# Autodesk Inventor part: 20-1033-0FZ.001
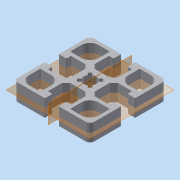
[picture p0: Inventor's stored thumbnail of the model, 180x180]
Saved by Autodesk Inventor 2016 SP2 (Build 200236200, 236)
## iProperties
Created: 2007-12
Document SubType Name: Modeling
Designer: Administrator
Density: 2.75 g/cm^3
Material: EN AW-6063 T66
Description: Profil 45x45 F
Mass: 20.4209 g
Surface Area: 68.0612 cm^2
Volume: 7.4258 cm^3
Part Number: 20-1033-0FZ.001
Vendor: MiniTec
Appearance: Aluminium - flach - Version 1.1
M8x20_Stck: 0
PV_Stck: 0
Länge: 10.0 mm
Lieferantennr: 72401
Zeichnungsnr: 20-1033-0FZ.001
MiniTec_ID: 201033/0
Teileart: ART
Lieferant: MiniTec™
Bezeichnung: Profil 45x45 F
Artikelnr: 201033/0
Bemerkung: eloxiert E6/EV1
M10x25_Stck: 0
M12_Stck: 0
BfGv_Stck: 0
Title: Profil 45x45 F
Author: Administrator
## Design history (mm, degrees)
sketch "Skizze1"
  geometry: L1 (-22.2, 4.1)-(-18.5, 4.1); L2 (-18, 4.6)-(-18, 6.5); L3 (-17.7, 6.8)-(-9.5, 6.8); L4 (-9.5, 6.8)-(-7.2, 4.5); L5 (-7.2, 4.5)-(-7.2, -4.5); L6 (-7.2, -4.5)-(-9.5, -6.8); L7 (-9.5, -6.8)-(-17.7, -6.8); L8 (-18, -6.5)-(-18, -4.6); L9 (-18.5, -4.1)-(-22.2, -4.1); L10 (-22.5, 4.4)-(-22.5, 20); L11 (-22.5, -20)-(-22.5, -4.4); L12 (-4.4, -22.5)-(-20, -22.5); L13 (-4.1, -22.2)-(-4.1, -18.5); L14 (-4.6, -18)-(-6.5, -18); L15 (-6.8, -17.7)-(-6.8, -9.5); L16 (-6.8, -9.5)-(-4.5, -7.2); L17 (-4.5, -7.2)-(4.5, -7.2); L18 (4.5, -7.2)-(6.8, -9.5); L19 (6.8, -9.5)-(6.8, -17.7); L20 (6.5, -18)-(4.6, -18); L21 (4.1, -18.5)-(4.1, -22.2); L22 (20, -22.5)-(4.4, -22.5); L23 (22.5, -4.4)-(22.5, -20); L24 (22.2, -4.1)-(18.5, -4.1); L25 (18, -4.6)-(18, -6.5); L26 (17.7, -6.8)-(9.5, -6.8); L27 (9.5, -6.8)-(7.2, -4.5); L28 (7.2, -4.5)-(7.2, 4.5); L29 (7.2, 4.5)-(9.5, 6.8); L30 (9.5, 6.8)-(17.7, 6.8); L31 (18, 6.5)-(18, 4.6); L32 (18.5, 4.1)-(22.2, 4.1); L33 (22.5, 20)-(22.5, 4.4); L34 (4.4, 22.5)-(20, 22.5); L35 (4.1, 22.2)-(4.1, 18.5); L36 (4.6, 18)-(6.5, 18); L37 (6.8, 17.7)-(6.8, 9.5); L38 (6.8, 9.5)-(4.5, 7.2); L39 (4.5, 7.2)-(-4.5, 7.2); L40 (-4.5, 7.2)-(-6.8, 9.5); L41 (-6.8, 9.5)-(-6.8, 17.7); L42 (-6.5, 18)-(-4.6, 18); L43 (-4.1, 18.5)-(-4.1, 22.2); L44 (-20, 22.5)-(-4.4, 22.5); L45 (-2.97, 4.384)-(-2.005, 3.419); L46 (2.005, 3.419)-(2.97, 4.384); L47 (3.394, 4.384)-(4.384, 3.394); L48 (4.384, 2.97)-(3.419, 2.005); L49 (3.419, -2.005)-(4.384, -2.97); L50 (4.384, -3.394)-(3.394, -4.384); L51 (2.97, -4.384)-(2.005, -3.419); L52 (-2.005, -3.419)-(-2.97, -4.384); L53 (-3.394, -4.384)-(-4.384, -3.394); L54 (-4.384, -2.97)-(-3.419, -2.005); L55 (-3.419, 2.005)-(-4.384, 2.97); L56 (-4.384, 3.394)-(-3.394, 4.384); L57 (-8.8, -13.8)-(-8.8, -20); L58 (-9.3, -20.5)-(-15.5, -20.5); L59 (-20.5, -15.5)-(-20.5, -9.3); L60 (-20, -8.8)-(-13.8, -8.8); L61 (13.8, -8.8)-(20, -8.8); L62 (20.5, -9.3)-(20.5, -15.5); L63 (15.5, -20.5)-(9.3, -20.5); L64 (8.8, -20)-(8.8, -13.8)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; A1 r 0.3 centre (-22.2, 4.4) between (-22.5, 4.4) and (-22.2, 4.1); A2 r 0.5 centre (-18.5, 4.6) between (-18.5, 4.1) and (-18, 4.6); A3 r 0.3 centre (-17.7, 6.5) between (-17.7, 6.8) and (-18, 6.5); A4 r 0.3 centre (-17.7, -6.5) between (-18, -6.5) and (-17.7, -6.8); A5 r 0.5 centre (-18.5, -4.6) between (-18, -4.6) and (-18.5, -4.1); A6 r 0.3 centre (-22.2, -4.4) between (-22.2, -4.1) and (-22.5, -4.4); A7 r 2.5 centre (-20, -20) between (-22.5, -20) and (-20, -22.5); A8 r 0.3 centre (-4.4, -22.2) between (-4.4, -22.5) and (-4.1, -22.2); A9 r 0.5 centre (-4.6, -18.5) between (-4.1, -18.5) and (-4.6, -18); A10 r 0.3 centre (-6.5, -17.7) between (-6.8, -17.7) and (-6.5, -18); A11 r 0.3 centre (6.5, -17.7) between (6.5, -18) and (6.8, -17.7); A12 r 0.5 centre (4.6, -18.5) between (4.6, -18) and (4.1, -18.5); A13 r 0.3 centre (4.4, -22.2) between (4.1, -22.2) and (4.4, -22.5); A14 r 2.5 centre (20, -20) between (20, -22.5) and (22.5, -20); A15 r 0.3 centre (22.2, -4.4) between (22.5, -4.4) and (22.2, -4.1); A16 r 0.5 centre (18.5, -4.6) between (18.5, -4.1) and (18, -4.6); A17 r 0.3 centre (17.7, -6.5) between (17.7, -6.8) and (18, -6.5); A18 r 0.3 centre (17.7, 6.5) between (18, 6.5) and (17.7, 6.8); A19 r 0.5 centre (18.5, 4.6) between (18, 4.6) and (18.5, 4.1); A20 r 0.3 centre (22.2, 4.4) between (22.2, 4.1) and (22.5, 4.4); A21 r 2.5 centre (20, 20) between (22.5, 20) and (20, 22.5); A22 r 0.3 centre (4.4, 22.2) between (4.4, 22.5) and (4.1, 22.2); A23 r 0.5 centre (4.6, 18.5) between (4.1, 18.5) and (4.6, 18); A24 r 0.3 centre (6.5, 17.7) between (6.8, 17.7) and (6.5, 18); A25 r 0.3 centre (-6.5, 17.7) between (-6.5, 18) and (-6.8, 17.7); A26 r 0.5 centre (-4.6, 18.5) between (-4.6, 18) and (-4.1, 18.5); A27 r 0.3 centre (-4.4, 22.2) between (-4.1, 22.2) and (-4.4, 22.5); A28 r 2.5 centre (-20, 20) between (-20, 22.5) and (-22.5, 20); A29 r 0.3 centre (-1.793, 3.631) between (-2.005, 3.419) and (-1.66, 3.362); A30 r 3.75 centre (0, 0) between (1.66, 3.362) and (-1.66, 3.362); A31 r 0.3 centre (1.793, 3.631) between (1.66, 3.362) and (2.005, 3.419); A32 r 0.3 centre (3.182, 4.172) between (3.394, 4.384) and (2.97, 4.384); A33 r 0.3 centre (4.172, 3.182) between (4.384, 2.97) and (4.384, 3.394); A34 r 0.3 centre (3.631, 1.793) between (3.419, 2.005) and (3.362, 1.66); A35 r 3.75 centre (0, 0) between (3.362, -1.66) and (3.362, 1.66); A36 r 0.3 centre (3.631, -1.793) between (3.362, -1.66) and (3.419, -2.005); A37 r 0.3 centre (4.172, -3.182) between (4.384, -3.394) and (4.384, -2.97); A38 r 0.3 centre (3.182, -4.172) between (2.97, -4.384) and (3.394, -4.384); A39 r 0.3 centre (1.793, -3.631) between (2.005, -3.419) and (1.66, -3.362); A40 r 3.75 centre (0, 0) between (-1.66, -3.362) and (1.66, -3.362); A41 r 0.3 centre (-1.793, -3.631) between (-1.66, -3.362) and (-2.005, -3.419); A42 r 0.3 centre (-3.182, -4.172) between (-3.394, -4.384) and (-2.97, -4.384); A43 r 0.3 centre (-4.172, -3.182) between (-4.384, -2.97) and (-4.384, -3.394); A44 r 0.3 centre (-3.631, -1.793) between (-3.419, -2.005) and (-3.362, -1.66); A45 r 3.75 centre (0, 0) between (-3.362, 1.66) and (-3.362, -1.66); A46 r 0.3 centre (-3.631, 1.793) between (-3.362, 1.66) and (-3.419, 2.005); A47 r 0.3 centre (-4.172, 3.182) between (-4.384, 3.394) and (-4.384, 2.97); A48 r 0.3 centre (-3.182, 4.172) between (-2.97, 4.384) and (-3.394, 4.384); A49 r 5 centre (-13.8, -13.8) between (-8.8, -13.8) and (-13.8, -8.8); A50 r 0.5 centre (-9.3, -20) between (-9.3, -20.5) and (-8.8, -20); A51 r 5 centre (-15.5, -15.5) between (-20.5, -15.5) and (-15.5, -20.5); A52 r 0.5 centre (-20, -9.3) between (-20, -8.8) and (-20.5, -9.3); A53 r 5 centre (13.8, -13.8) between (13.8, -8.8) and (8.8, -13.8); A54 r 0.5 centre (20, -9.3) between (20.5, -9.3) and (20, -8.8); A55 r 5 centre (15.5, -15.5) between (15.5, -20.5) and (20.5, -15.5); A56 r 0.5 centre (9.3, -20) between (8.8, -20) and (9.3, -20.5); A57 r 5 centre (13.8, 13.8) between (8.8, 13.8) and (13.8, 8.8); A58 r 0.5 centre (9.3, 20) between (9.3, 20.5) and (8.8, 20); A59 r 5 centre (15.5, 15.5) between (20.5, 15.5) and (15.5, 20.5); A60 r 0.5 centre (20, 9.3) between (20, 8.8) and (20.5, 9.3); A61 r 5 centre (-13.8, 13.8) between (-13.8, 8.8) and (-8.8, 13.8); A62 r 0.5 centre (-20, 9.3) between (-20.5, 9.3) and (-20, 8.8); A63 r 5 centre (-15.5, 15.5) between (-15.5, 20.5) and (-20.5, 15.5); A64 r 0.5 centre (-9.3, 20) between (-8.8, 20) and (-9.3, 20.5)
  constraints: 144 end point, 128 point on circle, 64 centre point
extrude "Extrusion1" new body sketch "Skizze1" taper "d1" = 0 deg; stored distance "do" = 10 (= Länge)
node "Volumenkörper1"
node "Volumenkörpern"
node "Oberflächenkörpern"
other parameters: "M8x20_Stck" = 0 [user parameter], "PV_Stck" = 0 [user parameter], "Länge" = 10 [user parameter; used in 1 equation term], "d17" = 0, "d18" = 0, "d19" = 0, "d21" = 0, "d22" = 0, "d23" = 0, "M10x25_Stck" = 0 [user parameter], "M12_Stck" = 0 [user parameter], "BfGv_Stck" = 0 [user parameter]
